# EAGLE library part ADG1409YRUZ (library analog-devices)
4 Ohm RON, 4-Channel, ±15 V/+12 V/±5 V iCMOS Multiplexers Source: 8x ADG1408_1409.pdf
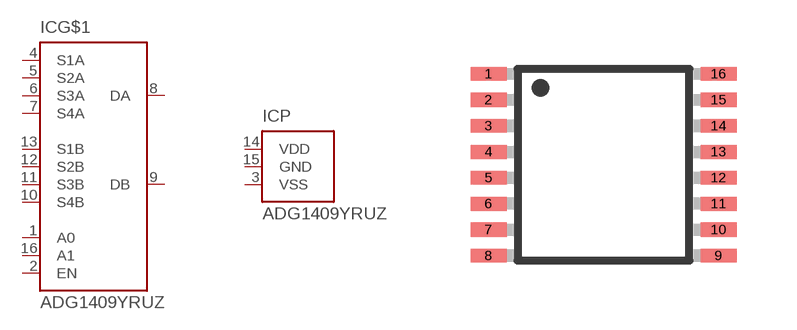
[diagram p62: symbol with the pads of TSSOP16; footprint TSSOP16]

Designator prefix IC; gates G$1=ADG1409 P=PWR-VSS_GND_VDD

## ADG1409YRUZ (MPN: ADG1409YRUZ; OC_FARNELL: 1438941; OC_NEWARK: 55M3850)  [TSSOP16]
1  G$1:A0  in
2  G$1:EN  in
3  P:VSS  pwr
4  G$1:S1A
5  G$1:S2A
6  G$1:S3A
7  G$1:S4A
8  G$1:DA
9  G$1:DB
10  G$1:S4B
11  G$1:S3B
12  G$1:S2B
13  G$1:S1B
14  P:VDD  pwr
15  P:GND  pwr
16  G$1:A1  in

## Footprint TSSOP16 (pad centres in mm)
16-Lead Thin Shrink Small Outline Package [TSSOP] (RU-16) Source: 8x ADG1408_1409.pdf
smd 0.9 x 0.35: 1 -2.875,2.275; 2 -2.875,1.625; 3 -2.875,0.975; 4 -2.875,0.325; 5 -2.875,-0.325; 6 -2.875,-0.975; 7 -2.875,-1.625; 8 -2.875,-2.275; 9 2.875,-2.275; 10 2.875,-1.625; 11 2.875,-0.975; 12 2.875,-0.325; 13 2.875,0.325; 14 2.875,0.975; 15 2.875,1.625; 16 2.875,2.275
